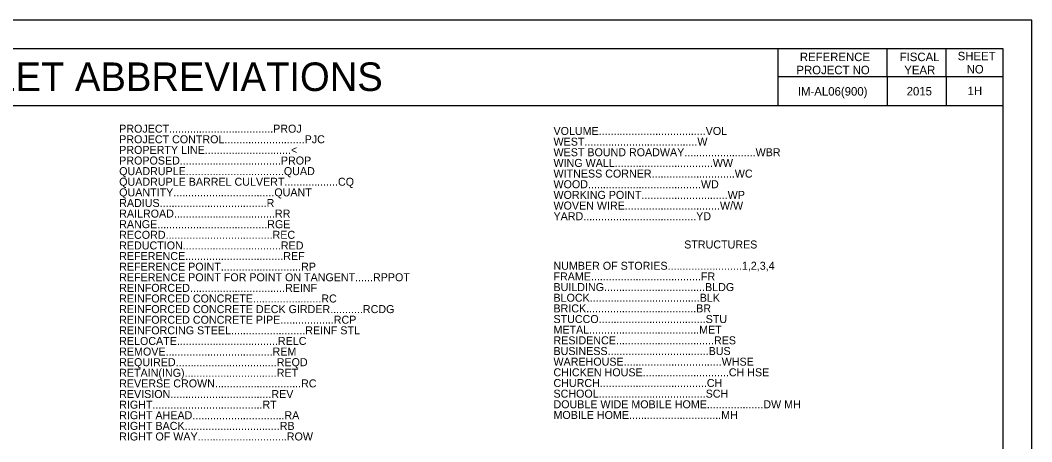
# Model space of a CAD drawing. Extents: x 0 to 1700, y 31 to 1131.
# Drawn here: x 815 to 1700, y 761 to 1131 of the extents above; entities that cross this region are included whole.
import ezdxf

# ---------------------------------------------------------------- set-up
doc = ezdxf.new("R2010")
doc.units = 0
for name, color, linetype in [('ANNO-SHT', 7, 'Continuous'), ('DRAINAGE', 7, 'Continuous'), ('LEGEND', 7, 'Continuous'), ('Level 1', 7, 'Continuous'), ('Level 6', 7, 'Continuous'), ('Level 62', 7, 'Continuous'), ('SHT-BDR', 7, 'Continuous'), ('SHT-BNDRY', 7, 'Continuous')]:
    doc.layers.add(name, color=color, linetype=linetype)

# ---------------------------------------------------------------- blocks, each defined once
blk = doc.blocks.new('SC47208')
at = {"layer": 'Level 1'}
blk.add_line((0, 0), (0, 0), dxfattribs=at)

msp = doc.modelspace()

# ---------------------------------------------------------------- linework, layer by layer
at = {"layer": 'Level 6'}
for p, q in [((1477.72, 1105.66), (1477.72, 1055.71)), ((1573.54, 1080.67), (1573.54, 1105.67)), ((1624.99, 1081.32), (1624.99, 1105.67)), ((1675, 1080.96), (1477.72, 1080.96)), ((1573.54, 1080.67), (1573.54, 1055.71)), ((1624.99, 1081.32), (1624.99, 1055.71)), ((1675, 1055.71), (1483.77, 1055.71))]:
    msp.add_line(p, q, dxfattribs=at)
at = {"layer": 'Level 62'}
msp.add_lwpolyline([(0, 30.66), (1700, 30.66), (1700, 1130.66), (0, 1130.66)], close=True, dxfattribs=at)
at = {"layer": 'SHT-BDR'}
msp.add_lwpolyline([(1675, 1055.71), (62.5, 1055.71)], dxfattribs=at)
at = {"layer": 'SHT-BNDRY'}
msp.add_lwpolyline([(62.5, 55.66), (1675, 55.66), (1675, 1105.66), (62.5, 1105.66)], close=True, dxfattribs=at)

# ---------------------------------------------------------------- block references
at = {"layer": 'DRAINAGE', "rotation": -116.41666666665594}
msp.add_blockref('SC47208', (876.59, 1081.65), dxfattribs=at)
msp.add_blockref('SC47208', (876.59, 1081.65), dxfattribs=at)

# ---------------------------------------------------------------- texts
at = {"layer": 'ANNO-SHT'}
for s, height, p in [('PLANS LEGEND SHEET ABBREVIATIONS', 24.9975, (476.45, 1068.67)), ('IM-AL06(900)', 7.4493, (1495.34, 1064.61)), ('2015', 7.449, (1590.53, 1064.77)), ('1H', 7.449, (1643.83, 1065.07))]:
    msp.add_text(s, height=height, dxfattribs=at).set_placement(p)
at = {"layer": 'LEGEND'}
msp.add_text('STRUCTURES', height=7, dxfattribs=at).set_placement((1395.92, 930.75))
at = {"layer": 'Level 1'}
for s, p in [('PROJECT...................................PROJ', (901.56, 1032.17)), ('VOLUME....................................VOL', (1281.56, 1030.17)), ('PROJECT CONTROL...........................PJC', (901.56, 1022.88)), ('WEST......................................W', (1281.56, 1020.83)), ('PROPERTY LINE.............................<', (901.56, 1013.58)), ('WEST BOUND ROADWAY........................WBR', (1281.56, 1011.5)), ('PROPOSED..................................PROP', (901.56, 1004.28)), ('WING WALL.................................WW', (1281.56, 1002.17)), ('QUADRUPLE.................................QUAD', (901.56, 994.99)), ('QUADRUPLE BARREL CULVERT..................CQ', (901.56, 985.69)), ('WITNESS CORNER............................WC', (1281.56, 992.83)), ('QUANTITY..................................QUANT', (901.56, 976.4)), ('WOOD......................................WD', (1281.56, 983.5)), ('RADIUS....................................R', (901.56, 967.1)), ('WORKING POINT.............................WP', (1281.56, 974.17)), ('RAILROAD..................................RR', (901.56, 957.8)), ('WOVEN WIRE................................W/W', (1281.56, 964.83)), ('YARD......................................YD', (1281.56, 955.5)), ('RANGE.....................................RGE', (901.56, 948.51)), ('RECORD....................................REC', (901.56, 939.21)), ('REDUCTION.................................RED', (901.56, 929.92)), ('REFERENCE.................................REF', (901.56, 920.62)), ('REFERENCE POINT...........................RP', (901.56, 911.32)), ('NUMBER OF STORIES.........................1,2,3,4', (1281.53, 912.11)), ('REFERENCE POINT FOR POINT ON TANGENT......RPPOT', (901.56, 902.03)), ('FRAME.....................................FR', (1281.53, 902.78)), ('REINFORCED................................REINF', (901.56, 892.73)), ('BUILDING..................................BLDG', (1281.53, 893.44)), ('REINFORCED CONCRETE.......................RC', (901.56, 883.44)), ('BLOCK.....................................BLK', (1281.53, 884.11)), ('REINFORCED CONCRETE DECK GIRDER...........RCDG', (901.56, 874.14)), ('BRICK.....................................BR', (1281.53, 874.78)), ('REINFORCED CONCRETE PIPE..................RCP', (901.56, 864.84)), ('STUCCO....................................STU', (1281.53, 865.44)), ('REINFORCING STEEL.........................REINF STL', (901.56, 855.55)), ('METAL.....................................MET', (1281.53, 856.11)), ('RELOCATE..................................RELC', (901.56, 846.25)), ('RESIDENCE.................................RES', (1281.53, 846.78)), ('REMOVE....................................REM', (901.56, 836.96)), ('BUSINESS..................................BUS', (1281.53, 837.44)), ('REQUIRED..................................REQD', (901.56, 827.66)), ('WAREHOUSE.................................WHSE', (1281.53, 828.11)), ('RETAIN(ING)...............................RET', (901.56, 818.36)), ('CHICKEN HOUSE.............................CH HSE', (1281.53, 818.78)), ('REVERSE CROWN.............................RC', (901.56, 809.07)), ('CHURCH....................................CH', (1281.53, 809.44)), ('REVISION..................................REV', (901.56, 799.77)), ('SCHOOL....................................SCH', (1281.53, 800.11)), ('RIGHT.....................................RT', (901.56, 790.48)), ('DOUBLE WIDE MOBILE HOME...................DW MH', (1281.53, 790.78)), ('RIGHT AHEAD...............................RA', (901.56, 781.18)), ('MOBILE HOME...............................MH', (1281.53, 781.44)), ('RIGHT BACK................................RB', (901.56, 771.88)), ('RIGHT OF WAY..............................ROW', (901.56, 762.59))]:
    msp.add_text(s, height=7, dxfattribs=at).set_placement(p)
at = {"layer": 'Level 6'}
for s, p in [('REFERENCE', (1497.09, 1094.82)), ('FISCAL', (1584.44, 1094.82)), ('SHEET', (1635.17, 1095.52)), ('PROJECT NO', (1494.08, 1083.32)), ('YEAR', (1588.44, 1083.32)), ('NO', (1643.02, 1084.02))]:
    msp.add_text(s, height=7.441, dxfattribs=at).set_placement(p)

doc.saveas('drawing.dxf')
